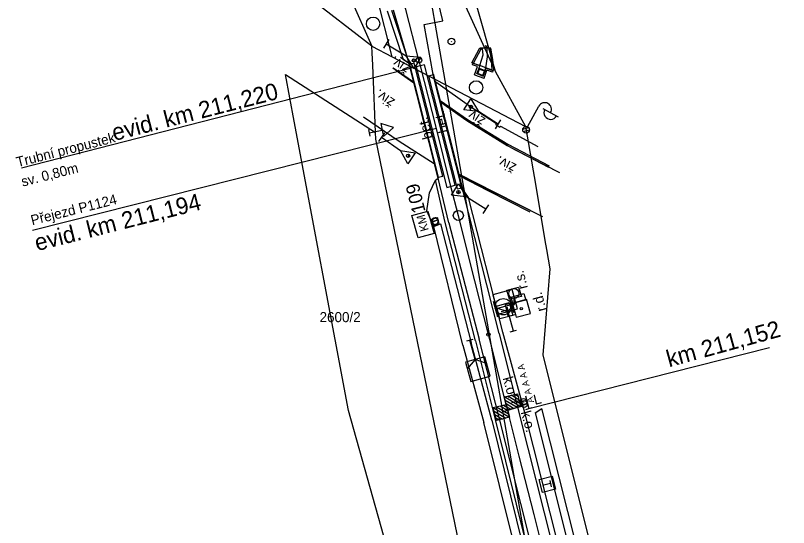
# Model space of a CAD drawing. Extents: x -754679 to -754173, y -1169241 to -1168288.
# Drawn here: x -754573.6 to -754458.2, y -1168520.4 to -1168443.9 of the extents above; entities that cross this region are included whole.
import ezdxf

# ---------------------------------------------------------------- set-up
doc = ezdxf.new("R2010")
doc.units = 0
for name, color, linetype in [('Vrstva 1', 7, 'Continuous'), ('Vrstva 11', 7, 'Continuous'), ('Vrstva 12', 7, 'Continuous'), ('Vrstva 16', 7, 'Continuous'), ('Vrstva 19', 7, 'Continuous'), ('Vrstva 23', 7, 'Continuous'), ('Vrstva 25', 7, 'Continuous'), ('Vrstva 27', 7, 'Continuous'), ('Vrstva 3', 7, 'Continuous'), ('Vrstva 33', 7, 'Continuous'), ('Vrstva 36', 7, 'Continuous'), ('Vrstva 4', 7, 'Continuous'), ('Vrstva 43', 7, 'Continuous'), ('Vrstva 49', 7, 'Continuous'), ('Vrstva 51', 7, 'Continuous'), ('Vrstva 53', 7, 'Continuous'), ('Vrstva 55', 7, 'Continuous'), ('Vrstva 57', 7, 'Continuous'), ('Vrstva 59', 7, 'Continuous'), ('Vrstva 6', 7, 'Continuous'), ('Vrstva 63', 7, 'Continuous'), ('Vrstva 7', 7, 'Continuous')]:
    doc.layers.add(name, color=color, linetype=linetype)

msp = doc.modelspace()

# ---------------------------------------------------------------- linework, layer by layer
at = {"layer": 'Vrstva 1'}
msp.add_line((-754513.14, -1168451.47), (-754513.35, -1168450.62), dxfattribs=at)
for points in [[(-754513.35, -1168450.62), (-754515.29, -1168443.04), (-754517.54, -1168434.32), (-754517.92, -1168432.84), (-754519.83, -1168425.59), (-754522.16, -1168416.85), (-754524.53, -1168408.11), (-754526.91, -1168399.43), (-754528.18, -1168394.85), (-754528.89, -1168392.32), (-754531.16, -1168384.27), (-754532.08, -1168381.05)], [(-754498.39, -1168509.75), (-754500.09, -1168503), (-754500.37, -1168501.89), (-754500.59, -1168501.05), (-754502.8, -1168492.33), (-754502.98, -1168491.62), (-754505.01, -1168483.59), (-754507.47, -1168473.86), (-754508.58, -1168469.47), (-754510.81, -1168460.63), (-754513.14, -1168451.47)], [(-754478.97, -1168586.46), (-754480.56, -1168580.17), (-754482.76, -1168571.47), (-754485.13, -1168562.12), (-754486.61, -1168556.26), (-754487.79, -1168551.61), (-754490, -1168542.89), (-754492.27, -1168533.93), (-754493.96, -1168527.25), (-754496.18, -1168518.51), (-754498.39, -1168509.75)]]:
    msp.add_lwpolyline(points, dxfattribs=at)
for centre, radius in [((-754513.35, -1168450.62), 0.4), ((-754502.98, -1168491.62), 0.25)]:
    msp.add_circle(centre, radius, dxfattribs=at)
at = {"layer": 'Vrstva 11'}
for p, q in [((-754511.59, -1168474.3), (-754511.35, -1168475.27)), ((-754510.62, -1168474.06), (-754510.38, -1168475.03)), ((-754510.5, -1168474.54), (-754511.47, -1168474.79))]:
    msp.add_line(p, q, dxfattribs=at)
at = {"layer": 'Vrstva 12'}
for p, q in [((-754511.07, -1168474.22), (-754511.05, -1168474.24)), ((-754511.38, -1168474.79), (-754511.47, -1168474.81)), ((-754510.89, -1168475.22), (-754510.83, -1168475.13)), ((-754510.44, -1168474.55), (-754510.51, -1168474.57))]:
    msp.add_line(p, q, dxfattribs=at)
for centre, major_axis, ratio, start_param, end_param in [((-754511.05, -1168474.73), (-0.119, 0.504), 0.826855, 6.048062, 9.524036), ((-754510.93, -1168474.69), (0.273, -0.37), 0.999682, 2.76009, 5.867568), ((-754510.83, -1168474.7), (0.12, -0.53), 0.771425, 5.875182, 9.712717), ((-754510.96, -1168474.69), (-0.275, -0.369), 0.999919, 0.916275, 3.979936)]:
    msp.add_ellipse(centre, major_axis=major_axis, ratio=ratio, start_param=start_param, end_param=end_param, dxfattribs=at)
at = {"layer": 'Vrstva 16'}
for p, q in [((-754511.13, -1168475.45), (-754512.18, -1168473.13)), ((-754511.13, -1168475.45), (-754510.13, -1168475.09)), ((-754506.81, -1168493.21), (-754511.13, -1168475.45)), ((-754510.13, -1168475.09), (-754505.57, -1168492.82)), ((-754499.42, -1168486.91), (-754500.49, -1168487.18)), ((-754500.49, -1168487.18), (-754500.07, -1168488.86)), ((-754500.07, -1168488.86), (-754498.95, -1168488.59)), ((-754502.48, -1168504.38), (-754505.57, -1168492.82)), ((-754506.81, -1168493.21), (-754503.69, -1168504.74)), ((-754496.02, -1168503.32), (-754494.99, -1168502.63)), ((-754487.09, -1168534.06), (-754494.99, -1168502.63)), ((-754502.48, -1168504.38), (-754495.81, -1168531.52)), ((-754496.02, -1168503.32), (-754488.52, -1168533.07))]:
    msp.add_line(p, q, dxfattribs=at)
for points in [[(-754512.18, -1168473.13), (-754511.76, -1168470.41), (-754510.89, -1168468.54)], [(-754498.52, -1168484.54), (-754498.07, -1168485.91), (-754499.86, -1168486.34), (-754500.24, -1168484.98), (-754498.52, -1168484.54)], [(-754495.69, -1168535.92), (-754496.62, -1168533.18), (-754503.69, -1168504.74)]]:
    msp.add_lwpolyline(points, dxfattribs=at)
at = {"layer": 'Vrstva 19'}
for p, q in [((-754505.44, -1168451), (-754504.33, -1168448.87)), ((-754505.21, -1168451.06), (-754504.06, -1168448.93)), ((-754504.33, -1168448.87), (-754504.22, -1168448.83)), ((-754504.06, -1168448.93), (-754504.33, -1168448.87)), ((-754503.18, -1168448.8), (-754504.22, -1168448.83)), ((-754504.22, -1168448.83), (-754503.89, -1168448.92)), ((-754504.06, -1168448.93), (-754503.89, -1168448.92)), ((-754503.78, -1168449.84), (-754503.89, -1168448.92)), ((-754502.81, -1168448.81), (-754503.18, -1168448.8)), ((-754503.11, -1168450.12), (-754503.18, -1168448.8)), ((-754502.64, -1168448.82), (-754503.18, -1168448.8)), ((-754502.55, -1168450.51), (-754502.81, -1168448.81)), ((-754502.64, -1168448.82), (-754502.81, -1168448.81)), ((-754502.33, -1168450.52), (-754502.64, -1168448.82)), ((-754504.25, -1168451.43), (-754503.78, -1168449.84)), ((-754503.37, -1168451.78), (-754503.11, -1168450.12)), ((-754505.27, -1168451.06), (-754505.29, -1168451.05)), ((-754505.21, -1168451.06), (-754504.25, -1168451.43)), ((-754502.41, -1168452.1), (-754502.55, -1168450.51)), ((-754502.16, -1168452.06), (-754502.33, -1168450.52)), ((-754513.14, -1168451.47), (-754572.7, -1168466.76)), ((-754505.07, -1168452.79), (-754504.62, -1168451.56)), ((-754504.37, -1168451.83), (-754504.25, -1168451.43)), ((-754504.37, -1168451.83), (-754504.3, -1168451.97)), ((-754504.29, -1168451.42), (-754504.25, -1168451.43)), ((-754503.64, -1168453.33), (-754503.2, -1168452.1)), ((-754503.51, -1168452.14), (-754503.58, -1168452.21)), ((-754503.33, -1168451.81), (-754503.37, -1168451.78)), ((-754502.41, -1168452.1), (-754503.37, -1168451.78)), ((-754502.31, -1168452.16), (-754502.29, -1168452.15)), ((-754504.71, -1168452.61), (-754503.78, -1168453.01)), ((-754504.71, -1168452.61), (-754504.7, -1168452.63)), ((-754504.7, -1168452.63), (-754504.59, -1168452.63))]:
    msp.add_line(p, q, dxfattribs=at)
for points in [[(-754505.21, -1168451.06), (-754505.29, -1168451.05), (-754505.44, -1168451)], [(-754504.62, -1168451.56), (-754505.37, -1168451.3), (-754505.27, -1168451.06), (-754504.29, -1168451.42), (-754504.71, -1168452.61)], [(-754504.7, -1168452.63), (-754504.37, -1168451.83), (-754503.51, -1168452.14), (-754503.8, -1168452.97), (-754504.7, -1168452.63)], [(-754504.59, -1168452.63), (-754504.3, -1168451.97), (-754503.58, -1168452.21), (-754503.86, -1168452.93), (-754504.21, -1168452.78), (-754504.59, -1168452.63)], [(-754503.51, -1168452.14), (-754503.37, -1168451.78), (-754504.25, -1168451.43)], [(-754503.78, -1168453.01), (-754503.33, -1168451.81), (-754502.31, -1168452.16), (-754502.4, -1168452.39), (-754502.4, -1168452.39), (-754503.2, -1168452.1)], [(-754502.41, -1168452.1), (-754502.29, -1168452.15), (-754502.16, -1168452.06)], [(-754505.07, -1168452.79), (-754503.65, -1168453.33), (-754503.64, -1168453.33)], [(-754503.78, -1168453.01), (-754503.8, -1168452.97), (-754503.86, -1168452.93)]]:
    msp.add_lwpolyline(points, dxfattribs=at)
at = {"layer": 'Vrstva 23'}
for p, q in [((-754499.42, -1168486.91), (-754497.31, -1168486.33)), ((-754496.71, -1168488.44), (-754497.31, -1168486.33)), ((-754498.83, -1168489.01), (-754496.71, -1168488.44))]:
    msp.add_line(p, q, dxfattribs=at)
msp.add_lwpolyline([(-754499.42, -1168486.91), (-754498.95, -1168488.59), (-754498.83, -1168489.01)], dxfattribs=at)
at = {"layer": 'Vrstva 25'}
for p, q in [((-754497.13, -1168460.57), (-754495.45, -1168457.49)), ((-754494.84, -1168457.83), (-754492.56, -1168459.07)), ((-754497.86, -1168460.91), (-754497.01, -1168460.66)), ((-754497.79, -1168461.28), (-754496.87, -1168461.01))]:
    msp.add_line(p, q, dxfattribs=at)
msp.add_lwpolyline([(-754499.35, -1168486.97), (-754499.61, -1168486.01), (-754497.68, -1168485.49), (-754497.42, -1168486.45), (-754499.35, -1168486.97)], dxfattribs=at)
msp.add_circle((-754497.37, -1168461.01), 0.5, dxfattribs=at)
for centre, start, end in [((-754494.58, -1168457.97), 331.4393, 151.4393), ((-754493.7, -1168458.46), 150.7367, 332.1418)]:
    msp.add_arc(centre, 1, start, end, dxfattribs=at)
at = {"layer": 'Vrstva 27'}
for p, q in [((-754497.75, -1168501.6), (-754497.72, -1168501.7)), ((-754497.68, -1168501.94), (-754497.65, -1168502.03))]:
    msp.add_line(p, q, dxfattribs=at)
for points in [[(-754497.67, -1168501.98), (-754497.76, -1168502.04), (-754498.18, -1168502.37), (-754500.59, -1168503.1)], [(-754497.74, -1168501.65), (-754497.85, -1168501.69), (-754498.11, -1168501.53), (-754498.62, -1168501.57), (-754499.53, -1168501.81)]]:
    msp.add_lwpolyline(points, dxfattribs=at)
for centre in [(-754497.74, -1168501.65), (-754497.67, -1168501.98)]:
    msp.add_circle(centre, 0.5, dxfattribs=at)
at = {"layer": 'Vrstva 3'}
for p, q in [((-754499.9, -1168485.94), (-754499.25, -1168488.32)), ((-754502.28, -1168486.6), (-754501.63, -1168488.97)), ((-754501.95, -1168487.78), (-754499.58, -1168487.13)), ((-754498.19, -1168502.39), (-754500.61, -1168500.92)), ((-754498.32, -1168501.88), (-754500.09, -1168500.8)), ((-754498.44, -1168501.36), (-754499.58, -1168500.67)), ((-754498.57, -1168500.84), (-754499.06, -1168500.54)), ((-754498.71, -1168502.52), (-754500.48, -1168501.44)), ((-754499.22, -1168502.64), (-754500.36, -1168501.95)), ((-754502.28, -1168502.51), (-754499.85, -1168503.97)), ((-754502.15, -1168503.03), (-754500.37, -1168504.1)), ((-754501.76, -1168502.38), (-754499.98, -1168503.46)), ((-754501.25, -1168502.26), (-754500.11, -1168502.94)), ((-754500.73, -1168502.13), (-754500.24, -1168502.43)), ((-754499.74, -1168502.77), (-754500.23, -1168502.47)), ((-754502.02, -1168503.54), (-754500.88, -1168504.23)), ((-754501.89, -1168504.06), (-754501.4, -1168504.35))]:
    msp.add_line(p, q, dxfattribs=at)
for points in [[(-754500.14, -1168502.86), (-754500.61, -1168500.92), (-754498.67, -1168500.45), (-754498.19, -1168502.39)], [(-754500.34, -1168502.03), (-754499.85, -1168503.97), (-754501.79, -1168504.45), (-754502.28, -1168502.51)]]:
    msp.add_lwpolyline(points, close=True, dxfattribs=at)
msp.add_circle((-754500.76, -1168487.45), 1.23, dxfattribs=at)
at = {"layer": 'Vrstva 33'}
for p, q in [((-754500.1, -1168487.94), (-754501.07, -1168488.19)), ((-754500.23, -1168487.45), (-754499.97, -1168488.42)), ((-754493.84, -1168513.39), (-754493.6, -1168514.36)), ((-754493.72, -1168513.87), (-754494.69, -1168514.11))]:
    msp.add_line(p, q, dxfattribs=at)
for points in [[(-754499.87, -1168486.84), (-754499.36, -1168488.78), (-754501.3, -1168489.28), (-754501.8, -1168487.35), (-754499.87, -1168486.84)], [(-754493.47, -1168512.78), (-754492.99, -1168514.72), (-754494.93, -1168515.2), (-754495.42, -1168513.26), (-754493.47, -1168512.78)]]:
    msp.add_lwpolyline(points, dxfattribs=at)
at = {"layer": 'Vrstva 36'}
for p, q in [((-754508.54, -1168447.78), (-754508.49, -1168447.87)), ((-754499.19, -1168486.22), (-754499.19, -1168487.22))]:
    msp.add_line(p, q, dxfattribs=at)
for centre, radius in [((-754508.51, -1168447.83), 0.5), ((-754499.19, -1168485.47), 0.757)]:
    msp.add_circle(centre, radius, dxfattribs=at)
at = {"layer": 'Vrstva 4'}
for p, q in [((-754517.46, -1168443.17), (-754514.8, -1168451.12)), ((-754514.8, -1168451.12), (-754517.18, -1168443.16)), ((-754515.65, -1168450.55), (-754518.06, -1168443.28)), ((-754512.57, -1168445.31), (-754509.79, -1168444.75)), ((-754511.22, -1168452.77), (-754512.57, -1168445.31)), ((-754517.86, -1168447.51), (-754518.66, -1168448.84)), ((-754514.8, -1168451.12), (-754515.65, -1168450.55)), ((-754514.16, -1168450.42), (-754514.04, -1168450.89)), ((-754505.57, -1168457.84), (-754505.67, -1168457.36)), ((-754501.95, -1168460.85), (-754501.11, -1168459.54)), ((-754510.76, -1168460.83), (-754571.05, -1168476.05)), ((-754518.49, -1168461.48), (-754519.39, -1168462.75)), ((-754515.01, -1168464.64), (-754514.93, -1168465.13)), ((-754510.89, -1168468.54), (-754510.47, -1168468.26)), ((-754509.45, -1168474.86), (-754510.89, -1168468.54)), ((-754508.88, -1168474.9), (-754510.47, -1168468.26)), ((-754507.42, -1168470.56), (-754507.52, -1168470.08)), ((-754501.4, -1168491.43), (-754506.85, -1168469.86)), ((-754505.96, -1168471.15), (-754506.85, -1168469.86)), ((-754500.85, -1168491.23), (-754505.96, -1168471.15)), ((-754503.77, -1168473.53), (-754502.94, -1168472.22)), ((-754504.93, -1168492.55), (-754509.45, -1168474.86)), ((-754508.88, -1168474.9), (-754504.39, -1168492.29)), ((-754501.4, -1168491.43), (-754498.34, -1168503.66)), ((-754497.49, -1168503.47), (-754500.85, -1168491.23)), ((-754504.93, -1168492.55), (-754501.99, -1168504.3)), ((-754501.32, -1168504.2), (-754504.39, -1168492.29)), ((-754501.99, -1168504.3), (-754494.47, -1168534.44)), ((-754493.78, -1168534.21), (-754501.32, -1168504.2)), ((-754498.34, -1168503.66), (-754490.79, -1168533.41)), ((-754490, -1168533.07), (-754497.49, -1168503.47))]:
    msp.add_line(p, q, dxfattribs=at)
for points in [[(-754509.79, -1168444.75), (-754512.46, -1168433.52), (-754510.83, -1168432.99), (-754510.11, -1168431.07), (-754511.04, -1168427.82), (-754509.74, -1168427.31), (-754510.9, -1168422.41)], [(-754518.26, -1168448.18), (-754515.28, -1168449.98), (-754513.06, -1168450.17), (-754514.08, -1168451.88), (-754515.28, -1168449.98)], [(-754510.53, -1168468.3), (-754510.46, -1168468.29), (-754512.51, -1168460.21), (-754514.81, -1168451.14), (-754514.87, -1168451.15), (-754512.59, -1168460.12), (-754510.53, -1168468.3)], [(-754514.06, -1168451.09), (-754514.76, -1168451.26), (-754514.76, -1168451.27), (-754510.48, -1168468.11), (-754509.79, -1168467.94), (-754514.06, -1168451.09)], [(-754509.19, -1168469.62), (-754507.95, -1168469.31), (-754512.52, -1168451.3), (-754513.76, -1168451.61), (-754513.75, -1168451.63), (-754509.19, -1168469.62)], [(-754511.21, -1168452.83), (-754511.91, -1168453), (-754507.64, -1168469.85), (-754506.94, -1168469.68), (-754511.21, -1168452.83)], [(-754506.88, -1168469.86), (-754506.82, -1168469.85), (-754508.62, -1168462.7), (-754511.17, -1168452.73), (-754511.22, -1168452.75), (-754508.69, -1168462.69), (-754506.88, -1168469.86)], [(-754501.53, -1168460.19), (-754504.45, -1168458.31), (-754506.67, -1168458.05), (-754505.59, -1168456.37), (-754504.45, -1168458.31)], [(-754518.94, -1168462.12), (-754516.1, -1168464.12), (-754513.9, -1168464.48), (-754515.04, -1168466.11), (-754516.1, -1168464.12)], [(-754503.36, -1168472.88), (-754506.3, -1168471.02), (-754508.52, -1168470.79), (-754507.46, -1168469.09), (-754506.3, -1168471.02)]]:
    msp.add_lwpolyline(points, dxfattribs=at)
for centre in [(-754514.1, -1168450.65), (-754505.61, -1168457.6), (-754514.97, -1168464.89), (-754507.47, -1168470.32)]:
    msp.add_circle(centre, 0.248, dxfattribs=at)
at = {"layer": 'Vrstva 43'}
for centre in [(-754520.2, -1168445.17), (-754504.83, -1168454.69)]:
    msp.add_circle(centre, 1, dxfattribs=at)
at = {"layer": 'Vrstva 49'}
for p, q in [((-754503.46, -1168448.44), (-754503.11, -1168448.79)), ((-754503.46, -1168448.79), (-754503.11, -1168448.44))]:
    msp.add_line(p, q, dxfattribs=at)
at = {"layer": 'Vrstva 51'}
for p, q in [((-754514.83, -1168451.1), (-754516.13, -1168450.23)), ((-754514.83, -1168451.1), (-754514.81, -1168451.14)), ((-754501.19, -1168460.5), (-754495.62, -1168463.53)), ((-754520.91, -1168460.98), (-754520.7, -1168461.96))]:
    msp.add_line(p, q, dxfattribs=at)
for points in [[(-754514.14, -1168454.04), (-754514.16, -1168454.02), (-754517.27, -1168451.82)], [(-754517.2, -1168451.74), (-754514.19, -1168453.87), (-754514.18, -1168453.88)], [(-754514.13, -1168454.06), (-754514.14, -1168454.05), (-754516.48, -1168452.41)], [(-754501.19, -1168460.5), (-754501.3, -1168460.66), (-754501.89, -1168460.29), (-754501.79, -1168460.12), (-754505.47, -1168457.75), (-754510.85, -1168453.92), (-754510.87, -1168453.91)], [(-754510.17, -1168456.64), (-754510.17, -1168456.64), (-754506.11, -1168459.48), (-754500.11, -1168463.17), (-754493.92, -1168466.42)], [(-754510.1, -1168456.89), (-754510.08, -1168456.91), (-754506.22, -1168459.63), (-754500.2, -1168463.35), (-754494.01, -1168466.58)], [(-754492.32, -1168467.44), (-754498.92, -1168464.07), (-754500.2, -1168463.35), (-754506.24, -1168459.64), (-754510.08, -1168456.92), (-754510.1, -1168456.9)], [(-754511.09, -1168466.1), (-754516.31, -1168462.76), (-754521.65, -1168459.11)], [(-754520.81, -1168461.47), (-754518.85, -1168461.05), (-754518.64, -1168462.02), (-754517.14, -1168460.68), (-754519.06, -1168460.07), (-754518.85, -1168461.05)], [(-754507.37, -1168467.66), (-754507.36, -1168467.67), (-754502.08, -1168470.36), (-754494.91, -1168473.97)], [(-754507.37, -1168467.67), (-754507.35, -1168467.68), (-754502.97, -1168469.92), (-754496.72, -1168473.09), (-754496.72, -1168473.09)], [(-754507.31, -1168467.91), (-754507.29, -1168467.92), (-754503.06, -1168470.09), (-754496.81, -1168473.26)]]:
    msp.add_lwpolyline(points, dxfattribs=at)
at = {"layer": 'Vrstva 53'}
for p, q in [((-754516.22, -1168402.04), (-754501.97, -1168452.25)), ((-754520.37, -1168448.54), (-754569.24, -1168410.61)), ((-754520.33, -1168449.52), (-754520.37, -1168448.54)), ((-754520.25, -1168451.35), (-754520.33, -1168449.52)), ((-754519.95, -1168458.75), (-754520.25, -1168451.35)), ((-754501.97, -1168452.25), (-754497.45, -1168460.53)), ((-754531.99, -1168459.75), (-754533.3, -1168452.78)), ((-754533.3, -1168452.78), (-754519.84, -1168461.42)), ((-754519.84, -1168461.42), (-754519.95, -1168458.75)), ((-754523.85, -1168502.96), (-754531.99, -1168459.75)), ((-754497.45, -1168460.53), (-754496.32, -1168467.13)), ((-754496.32, -1168467.13), (-754496.03, -1168468.86)), ((-754496.03, -1168468.86), (-754494.55, -1168477.55)), ((-754494.55, -1168477.55), (-754494.32, -1168478.89)), ((-754494.32, -1168478.89), (-754493.82, -1168481.8)), ((-754493.82, -1168481.8), (-754494.84, -1168494.63)), ((-754494.84, -1168494.63), (-754483.21, -1168541.23)), ((-754490.14, -1168623.07), (-754523.85, -1168502.96))]:
    msp.add_line(p, q, dxfattribs=at)
at = {"layer": 'Vrstva 55'}
for p, q in [((-754517.36, -1168450.11), (-754535.97, -1168376.96)), ((-754525.37, -1168437.38), (-754520.37, -1168448.54)), ((-754506.68, -1168442.02), (-754501.97, -1168452.25)), ((-754520.37, -1168448.54), (-754517.36, -1168450.11)), ((-754517.36, -1168450.11), (-754497.45, -1168460.53)), ((-754519.8, -1168462.41), (-754519.84, -1168461.42)), ((-754486.32, -1168624.94), (-754519.8, -1168462.41))]:
    msp.add_line(p, q, dxfattribs=at)
at = {"layer": 'Vrstva 59'}
msp.add_circle((-754498.09, -1168487.73), 0.175, dxfattribs=at)
at = {"layer": 'Vrstva 6'}
for p, q in [((-754496.93, -1168502.65), (-754461.01, -1168493.56)), ((-754497.46, -1168500.74), (-754496.93, -1168502.65)), ((-754497.42, -1168502.78), (-754496.45, -1168502.52))]:
    msp.add_line(p, q, dxfattribs=at)
at = {"layer": 'Vrstva 63'}
msp.add_lwpolyline([(-754454.68, -1168695.98), (-754495.29, -1168534.73), (-754520.59, -1168389.67)], dxfattribs=at)
at = {"layer": 'Vrstva 7'}
for p, q in [((-754510.95, -1168474.68), (-754511.55, -1168474.85)), ((-754500.07, -1168488.17), (-754499.28, -1168491.06)), ((-754499.76, -1168491.2), (-754498.79, -1168490.93)), ((-754505.3, -1168492.32), (-754506.26, -1168492.59)), ((-754504.98, -1168495.35), (-754505.78, -1168492.46))]:
    msp.add_line(p, q, dxfattribs=at)
msp.add_lwpolyline([(-754511.09, -1168476.53), (-754513.48, -1168477.18), (-754514.41, -1168473.82), (-754512.01, -1168473.16)], close=True, dxfattribs=at)
for points in [[(-754500.07, -1168488.17), (-754498.63, -1168487.77), (-754499.42, -1168484.88), (-754502.31, -1168485.68), (-754501.52, -1168488.57), (-754500.07, -1168488.17)], [(-754501.78, -1168487.6), (-754500.07, -1168488.17), (-754498.89, -1168486.81)], [(-754504.98, -1168495.35), (-754506.43, -1168495.75), (-754505.63, -1168498.64), (-754502.74, -1168497.84), (-754503.54, -1168494.95), (-754504.98, -1168495.35)], [(-754503.27, -1168495.92), (-754504.98, -1168495.35), (-754506.16, -1168496.71)]]:
    msp.add_lwpolyline(points, dxfattribs=at)
msp.add_circle((-754507.48, -1168473.81), 0.75, dxfattribs=at)

# ---------------------------------------------------------------- texts
at = {"layer": 'Vrstva 11'}
msp.add_text('109', height=2, rotation=104.1901, dxfattribs=at).set_placement((-754512.35, -1168473.2))
at = {"layer": 'Vrstva 19'}
for s, height, p in [('evid. km 211,220', 2.5, (-754558.83, -1168462.7)), ('Trubní propustek', 1.5, (-754573.26, -1168466.61)), ('sv. 0,80m', 1.5, (-754572.51, -1168469.52))]:
    msp.add_text(s, height=height, rotation=14.4012, dxfattribs=at).set_placement(p)
at = {"layer": 'Vrstva 23'}
msp.add_text('r.d.', height=1.5, rotation=105.7615, dxfattribs=at).set_placement((-754494.28, -1168487.93))
at = {"layer": 'Vrstva 25'}
msp.add_text('r.s.', height=1.5, rotation=104.2177, dxfattribs=at).set_placement((-754497.1, -1168484.62))
at = {"layer": 'Vrstva 27'}
for p in [(-754500.86, -1168498.12), (-754498.17, -1168503.22)]:
    msp.add_text('k.o.', height=1.5, rotation=285.3513, dxfattribs=at).set_placement(p)
at = {"layer": 'Vrstva 4'}
for s, height, rotation, p in [('bet.', 1.5, 103.5731, (-754508.9, -1168461.29)), ('bet.', 1.5, 104.2881, (-754511.29, -1168462.23)), ('Přejezd P1124', 1.5, 14.1734, (-754571.09, -1168475.29)), ('evid. km 211,194', 2.5, 14.2257, (-754570.37, -1168479.15))]:
    msp.add_text(s, height=height, rotation=rotation, dxfattribs=at).set_placement(p)
at = {"layer": 'Vrstva 51'}
for rotation, p in [(146.3099, (-754514.54, -1168451.58)), (144.8847, (-754516.83, -1168456.58)), (147.098, (-754503.32, -1168459.36)), (152.9301, (-754498.69, -1168466.22))]:
    msp.add_text('živ.', height=1.5, rotation=rotation, dxfattribs=at).set_placement(p)
at = {"layer": 'Vrstva 57'}
msp.add_text('2600/2', height=1.5, dxfattribs=at).set_placement((-754528.19, -1168489.75))
at = {"layer": 'Vrstva 6'}
for s, height, rotation, p in [('km 211,152', 2.5, 15.3838, (-754476.02, -1168496.5)), ('  A A A A A ', 1, 105.3838, (-754495.97, -1168502.39)), ('L', 1.5, 14.1581, (-754496.04, -1168502.12))]:
    msp.add_text(s, height=height, rotation=rotation, dxfattribs=at).set_placement(p)
at = {"layer": 'Vrstva 7'}
msp.add_text('KM', height=1.247, rotation=105.3838, dxfattribs=at).set_placement((-754511.88, -1168475.99))

doc.saveas('drawing.dxf')
